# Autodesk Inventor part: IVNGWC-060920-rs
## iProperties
Manager: Dr.-Ing. Roland Schröder
Company: www.Das-Entwicklungsbuero.de
Created: 2006-09
Part Number: IVNGWC-060920-rs
Project: 12107
Document SubType Name: Modeling
Designer: rsc
Engineer: Dr.-Ing. Roland Schröder
Oberflächen: Ra 6,4
Toleranzen: ISO 2768 - m
Kanten: brechen
Author: rsc
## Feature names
1. Drehung1 [Revolution]
2. Spirale1
3. Sweeping1
4. Runde Anordnung1 [Circular Pattern]
